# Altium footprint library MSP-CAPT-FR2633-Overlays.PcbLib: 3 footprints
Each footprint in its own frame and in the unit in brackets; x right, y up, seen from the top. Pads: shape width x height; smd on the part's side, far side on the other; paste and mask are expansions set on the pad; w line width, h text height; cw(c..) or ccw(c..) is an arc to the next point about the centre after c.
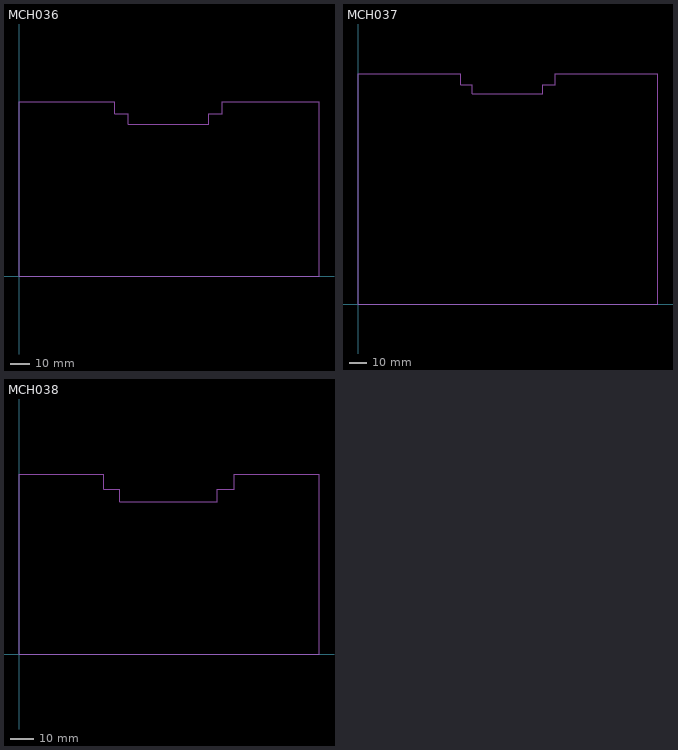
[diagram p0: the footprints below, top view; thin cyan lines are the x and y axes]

## MCH036 [mm] "CAPTIVATE-BSWP Overlay"
height 1.524
M5 Assembly Top:
  text ".Designator" at 0,-2.54 h1.02
M13 Component Bodies Top:
  lines w0.254: 0,0 152.4,0 152.4,88.9 103.378,88.9 103.378,82.55 96.52,82.55 96.52,77.216 55.372,77.216 55.372,82.55 48.514,82.55 48.514,88.9 0,88.9 0,0
3D body: height 1.52, standoff 0, extent 0,0 152.4,88.9

## MCH037 [mm] "CAPTIVATE-PHONE Overlay"
height 1.524
M5 Assembly Top:
  text ".Designator" at 0,-2.54 h1.02
M13 Component Bodies Top:
  lines w0.254: 0,0 0,134.62 59.944,134.62 59.944,128.27 66.802,128.27 66.802,122.936 107.95,122.936 107.95,128.27 115.316,128.27 115.316,134.62 175.26,134.62 175.26,0 0,0
3D body: height 1.52, standoff 0, extent 0,0 175.26,134.62

## MCH038 [mm] "CAPTIVATE-PROXIMITY Overlay"
height 1.524
M5 Assembly Top:
  text ".Designator" at 0,-2.54 h1.02
M13 Component Bodies Top:
  lines w0.254: 0,0 127,0 127,76.2 91.186,76.2 91.186,69.85 83.82,69.85 83.82,64.516 42.672,64.516 42.672,69.85 35.814,69.85 35.814,76.2 0,76.2 0,0
3D body: height 1.52, standoff 0, extent 0,0 127,76.2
